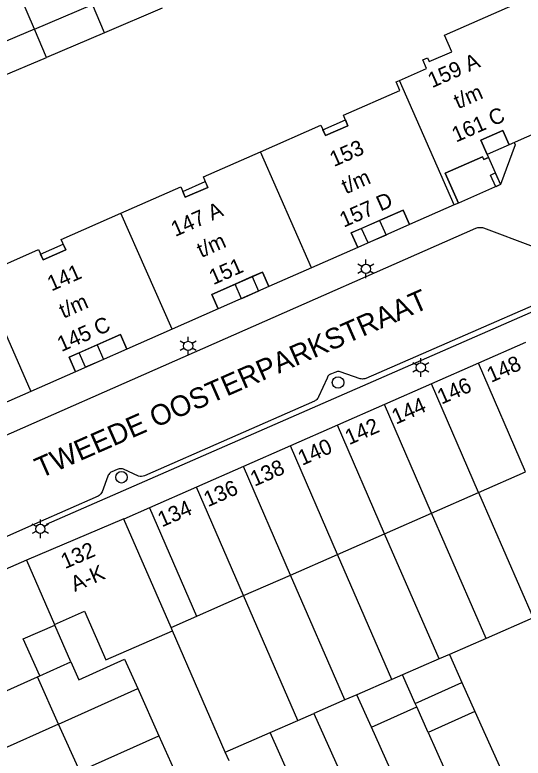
# Model space of a CAD drawing. Extents: x 122462 to 123306, y 485548 to 486417.
# Drawn here: x 123065.1 to 123114.5, y 485591 to 485663.3 of the extents above; entities that cross this region are included whole.
import ezdxf

# ---------------------------------------------------------------- set-up
doc = ezdxf.new("R2010")
doc.units = 0
for name, color, linetype in [('B-WE-IE-MEUBILAIR_WEGMEUBILAIR_VERKEERSBORD-S', 7, 'Continuous'), ('Level 1', 7, 'Continuous'), ('Level 10', 7, 'Continuous'), ('Level 11', 7, 'Continuous'), ('Level 17', 7, 'Continuous'), ('Level 19', 7, 'Continuous'), ('Level 2', 7, 'Continuous'), ('Level 30', 7, 'Continuous'), ('Level 34', 7, 'Continuous'), ('Level 4', 7, 'Continuous'), ('Level 50', 7, 'Continuous'), ('Level 53', 7, 'Continuous'), ('N-WE-AL-T25', 7, 'Continuous'), ('N-WE-GR-BOOM_DOORWORTELBARE RUIMTE-G', 7, 'Continuous')]:
    doc.layers.add(name, color=color, linetype=linetype)

msp = doc.modelspace()

# ---------------------------------------------------------------- linework, layer by layer
at = {"layer": 'Level 1'}
for p, q in [((123100.592, 485643.304), (123098.838, 485642.531)), ((123088.207, 485637.847), (123086.535, 485637.11)), ((123114.754, 485631.419), (123110.186, 485629.41)), ((123073.137, 485631.207), (123071.392, 485630.438)), ((123110.186, 485629.41), (123105.618, 485627.402)), ((123105.618, 485627.402), (123101.049, 485625.394)), ((123101.049, 485625.394), (123096.482, 485623.387)), ((123096.482, 485623.387), (123091.913, 485621.378)), ((123091.913, 485621.378), (123087.345, 485619.37)), ((123087.345, 485619.37), (123082.777, 485617.362)), ((123110.205, 485616.854), (123114.774, 485618.861)), ((123082.777, 485617.362), (123078.209, 485615.354)), ((123105.636, 485614.847), (123110.205, 485616.854)), ((123078.209, 485615.354), (123075.745, 485614.248)), ((123101.067, 485612.84), (123105.636, 485614.847)), ((123096.499, 485610.833), (123101.067, 485612.84)), ((123091.93, 485608.826), (123096.499, 485610.833)), ((123087.362, 485606.819), (123091.93, 485608.826)), ((123080.321, 485603.726), (123087.362, 485606.819)), ((123115.51, 485604.655), (123110.937, 485602.659)), ((123069.032, 485603.947), (123068.996, 485604.029)), ((123080.459, 485603.409), (123080.321, 485603.726)), ((123110.937, 485602.659), (123107.371, 485601.104)), ((123107.371, 485601.104), (123106.363, 485600.664)), ((123106.363, 485600.664), (123102.802, 485599.112)), ((123067.337, 485598.913), (123067.565, 485599.015)), ((123069.395, 485594.33), (123067.337, 485598.913)), ((123102.802, 485599.112), (123101.789, 485598.67)), ((123101.789, 485598.67), (123098.386, 485597.186)), ((123104.05, 485596.334), (123108.596, 485598.376)), ((123108.596, 485598.376), (123109.856, 485595.57)), ((123097.215, 485596.675), (123094.21, 485595.364)), ((123098.386, 485597.186), (123097.215, 485596.675)), ((123099.805, 485594.027), (123104.2, 485596.001)), ((123104.2, 485596.001), (123104.05, 485596.334)), ((123094.21, 485595.364), (123098.391, 485586.058)), ((123109.856, 485595.57), (123105.31, 485593.529)), ((123071.452, 485589.751), (123069.395, 485594.33)), ((123101.624, 485589.977), (123099.805, 485594.027)), ((123105.31, 485593.529), (123106.941, 485589.899))]:
    msp.add_line(p, q, dxfattribs=at)
for points in [[(123102.513, 485656.923), (123105.15, 485658.082), (123104.787, 485658.906), (123105.245, 485659.108), (123105.406, 485658.742), (123107.603, 485659.71), (123106.896, 485661.316), (123131.906, 485672.331), (123132.612, 485670.729), (123134.808, 485671.696), (123134.647, 485672.062), (123135.104, 485672.263), (123135.467, 485671.439), (123138.094, 485672.594)], [(123143.438, 485660.484), (123143.083, 485660.327), (123141.803, 485663.235), (123138.179, 485661.639), (123138.304, 485661.356), (123137.855, 485661.158), (123137.108, 485662.854), (123134.89, 485661.877), (123135.503, 485660.486), (123126.802, 485656.654), (123125.651, 485659.27), (123120.75, 485657.111), (123121.902, 485654.496), (123113.193, 485650.66), (123112.58, 485652.052), (123110.428, 485651.104), (123111.173, 485649.408), (123110.724, 485649.211), (123110.6, 485649.494), (123106.975, 485647.9), (123108.257, 485644.987), (123107.851, 485644.807)], [(123089.007, 485649.968), (123094.876, 485652.554), (123095.32, 485651.548), (123097.516, 485652.515), (123097.072, 485653.522), (123102.562, 485655.94), (123102.192, 485656.782), (123102.513, 485656.923)], [(123075.452, 485643.996), (123081.26, 485646.555), (123081.704, 485645.549), (123083.904, 485646.518), (123083.461, 485647.525), (123089.007, 485649.968)], [(123107.851, 485644.807), (123103.502, 485642.891), (123102.877, 485644.311), (123100.592, 485643.304)], [(123061.734, 485637.952), (123067.431, 485640.462), (123067.874, 485639.456), (123070.08, 485640.427), (123069.636, 485641.434), (123075.452, 485643.996)], [(123098.838, 485642.531), (123097.84, 485642.091), (123098.465, 485640.672), (123093.974, 485638.694)], [(123093.974, 485638.694), (123089.82, 485636.864), (123089.195, 485638.282), (123088.207, 485637.847)], [(123086.535, 485637.11), (123084.277, 485636.115), (123084.902, 485634.697), (123080.42, 485632.722)], [(123080.42, 485632.722), (123076.019, 485630.783), (123075.394, 485632.202), (123073.137, 485631.207)], [(123071.392, 485630.438), (123070.416, 485630.008), (123071.041, 485628.59), (123066.701, 485626.678)], [(123066.701, 485626.678), (123062.378, 485624.773), (123061.753, 485626.192), (123060.806, 485625.775)], [(123075.745, 485614.248), (123075.729, 485614.279), (123066.279, 485610.269)], [(123066.279, 485610.269), (123059.494, 485607.31), (123052.709, 485604.35), (123057.168, 485594.345)], [(123068.996, 485604.029), (123071.922, 485605.302), (123073.972, 485600.588), (123080.459, 485603.409)], [(123067.565, 485599.015), (123065.952, 485602.607), (123069.032, 485603.947)]]:
    msp.add_lwpolyline(points, dxfattribs=at)
at = {"layer": 'Level 10'}
for points in [[(123095.32, 485651.548), (123095.066, 485652.124), (123097.262, 485653.091), (123097.516, 485652.515), (123095.32, 485651.548)], [(123111.04, 485649.711), (123110.428, 485651.104), (123112.58, 485652.052), (123113.193, 485650.66), (123111.04, 485649.711)], [(123112.33, 485646.779), (123108.257, 485644.987), (123106.975, 485647.9), (123110.6, 485649.494), (123110.724, 485649.211), (123111.173, 485649.408), (123112.33, 485646.779)], [(123081.704, 485645.549), (123081.45, 485646.125), (123083.65, 485647.095), (123083.904, 485646.518), (123081.704, 485645.549)], [(123098.465, 485640.672), (123097.84, 485642.091), (123102.877, 485644.311), (123103.502, 485642.891), (123098.465, 485640.672)], [(123067.874, 485639.456), (123067.621, 485640.033), (123069.826, 485641.003), (123070.08, 485640.427), (123067.874, 485639.456)], [(123084.902, 485634.697), (123084.277, 485636.115), (123089.195, 485638.282), (123089.82, 485636.864), (123084.902, 485634.697)], [(123071.041, 485628.59), (123070.416, 485630.008), (123075.394, 485632.202), (123076.019, 485630.783), (123071.041, 485628.59)]]:
    msp.add_lwpolyline(points, dxfattribs=at)
at = {"layer": 'Level 11'}
msp.add_lwpolyline([(123113.663, 485650.867), (123113.762, 485650.642), (123112.33, 485646.779)], dxfattribs=at)
at = {"layer": 'Level 17'}
msp.add_line((123167.101, 485657.051), (123068.183, 485613.738), dxfattribs=at)
for points in [[(123059.035, 485620.111), (123109.941, 485642.545), (123110.044, 485642.584), (123110.151, 485642.612), (123110.26, 485642.627), (123110.37, 485642.63), (123110.48, 485642.622), (123110.588, 485642.601), (123110.693, 485642.568), (123115.505, 485640.78)], [(123116.786, 485635.597), (123108.895, 485632.144), (123099.244, 485627.943)], [(123099.244, 485627.943), (123099.138, 485627.909), (123099.028, 485627.889), (123098.917, 485627.882), (123098.806, 485627.889), (123098.697, 485627.91), (123096.759, 485628.582), (123096.672, 485628.603), (123096.583, 485628.611), (123096.493, 485628.607), (123096.405, 485628.591), (123096.32, 485628.563), (123096.239, 485628.524), (123095.913, 485628.394), (123095.827, 485628.37), (123095.745, 485628.331), (123095.672, 485628.28), (123095.607, 485628.218), (123095.554, 485628.146), (123095.513, 485628.066), (123095.486, 485627.98), (123094.65, 485626.139), (123094.606, 485626.053), (123094.551, 485625.973), (123094.487, 485625.901), (123094.413, 485625.838), (123094.333, 485625.785), (123094.246, 485625.742), (123077.738, 485618.461), (123077.597, 485618.43), (123077.453, 485618.413), (123077.309, 485618.412), (123077.165, 485618.427), (123075.689, 485619.107), (123075.592, 485619.136), (123075.493, 485619.153), (123075.392, 485619.157), (123075.291, 485619.149), (123075.193, 485619.129), (123075.097, 485619.096), (123074.553, 485618.857), (123074.469, 485618.811), (123074.392, 485618.754), (123074.322, 485618.688), (123074.262, 485618.614), (123074.212, 485618.532), (123074.172, 485618.445), (123073.619, 485616.904), (123073.56, 485616.806), (123073.49, 485616.716), (123073.411, 485616.634), (123073.322, 485616.562), (123073.225, 485616.501), (123067.352, 485613.901), (123058.667, 485610.037)]]:
    msp.add_lwpolyline(points, dxfattribs=at)
at = {"layer": 'Level 19'}
for p, q in [((123067.031, 485661.895), (123062.693, 485672.078)), ((123110.205, 485616.854), (123115.51, 485604.655)), ((123110.937, 485602.659), (123105.636, 485614.847)), ((123106.363, 485600.664), (123101.067, 485612.84)), ((123101.789, 485598.67), (123096.499, 485610.833)), ((123097.215, 485596.675), (123091.93, 485608.826)), ((123092.641, 485594.68), (123087.362, 485606.819)), ((123070.588, 485600.372), (123069.032, 485603.947)), ((123085.592, 485591.606), (123080.459, 485603.409)), ((123067.565, 485599.015), (123070.588, 485600.372)), ((123069.395, 485594.33), (123077.076, 485597.781)), ((123077.076, 485597.781), (123079.134, 485593.202)), ((123105.31, 485593.529), (123104.2, 485596.001)), ((123092.641, 485594.68), (123094.21, 485595.364)), ((123089.957, 485593.51), (123092.641, 485594.68)), ((123071.452, 485589.751), (123079.134, 485593.202)), ((123079.134, 485593.202), (123081.191, 485588.624)), ((123085.592, 485591.606), (123089.957, 485593.51)), ((123093.236, 485586.21), (123089.957, 485593.51)), ((123085.956, 485590.766), (123085.592, 485591.606))]:
    msp.add_line(p, q, dxfattribs=at)
msp.add_lwpolyline([(123070.588, 485600.372), (123071.34, 485598.644), (123075.789, 485600.644), (123077.076, 485597.781)], dxfattribs=at)
at = {"layer": 'Level 2'}
for p, q in [((123067.031, 485661.895), (123072.669, 485664.298)), ((123073.836, 485661.557), (123072.669, 485664.298)), ((123079.448, 485663.948), (123073.836, 485661.557)), ((123067.031, 485661.895), (123061.479, 485659.53)), ((123068.199, 485659.155), (123067.031, 485661.895)), ((123073.836, 485661.557), (123068.199, 485659.155)), ((123062.647, 485656.789), (123068.199, 485659.155))]:
    msp.add_line(p, q, dxfattribs=at)
at = {"layer": 'Level 30'}
for points in [[(123100.592, 485643.304), (123101.217, 485641.884), (123099.463, 485641.112), (123098.838, 485642.531)], [(123088.207, 485637.847), (123088.832, 485636.428), (123087.16, 485635.692), (123086.535, 485637.11)], [(123073.137, 485631.207), (123073.762, 485629.789), (123072.017, 485629.02), (123071.392, 485630.438)]]:
    msp.add_lwpolyline(points, dxfattribs=at)
at = {"layer": 'Level 34'}
msp.add_lwpolyline([(123111.882, 485646.583), (123111.382, 485647.718), (123111.831, 485647.916), (123112.33, 485646.779), (123111.882, 485646.583)], dxfattribs=at)
at = {"layer": 'Level 4'}
for p, q in [((123107.851, 485644.807), (123102.513, 485656.923)), ((123093.974, 485638.694), (123089.007, 485649.968)), ((123080.42, 485632.722), (123075.452, 485643.996)), ((123061.734, 485637.952), (123066.701, 485626.678)), ((123080.321, 485603.726), (123075.745, 485614.248)), ((123066.279, 485610.269), (123068.996, 485604.029)), ((123107.371, 485601.104), (123108.596, 485598.376)), ((123057.168, 485594.345), (123067.337, 485598.913)), ((123104.05, 485596.334), (123102.802, 485599.112)), ((123099.805, 485594.027), (123098.386, 485597.186)), ((123069.395, 485594.33), (123059.246, 485589.771))]:
    msp.add_line(p, q, dxfattribs=at)
at = {"layer": 'Level 50'}
for p, q in [((123099.262, 485639.038), (123099.262, 485639.488)), ((123098.872, 485638.813), (123098.482, 485639.038)), ((123100.041, 485639.038), (123099.651, 485638.813)), ((123098.872, 485638.363), (123098.482, 485638.138)), ((123099.262, 485637.688), (123099.262, 485638.138)), ((123100.041, 485638.138), (123099.651, 485638.363)), ((123081.59, 485631.324), (123081.2, 485631.549)), ((123081.98, 485631.549), (123081.98, 485631.999)), ((123082.759, 485631.549), (123082.369, 485631.324)), ((123081.59, 485630.874), (123081.2, 485630.649)), ((123081.98, 485630.199), (123081.98, 485630.649)), ((123082.759, 485630.649), (123082.369, 485630.874)), ((123104.591, 485629.456), (123104.591, 485629.906)), ((123104.201, 485629.231), (123103.811, 485629.456)), ((123105.37, 485629.456), (123104.98, 485629.231)), ((123104.201, 485628.781), (123103.811, 485628.556)), ((123104.591, 485628.106), (123104.591, 485628.556)), ((123105.37, 485628.556), (123104.98, 485628.781)), ((123067.616, 485613.759), (123067.616, 485614.209)), ((123067.226, 485613.534), (123066.836, 485613.759)), ((123068.395, 485613.759), (123068.005, 485613.534)), ((123067.226, 485613.084), (123066.836, 485612.859)), ((123067.616, 485612.409), (123067.616, 485612.859)), ((123068.395, 485612.859), (123068.005, 485613.084))]:
    msp.add_line(p, q, dxfattribs=at)
for centre in [(123099.262, 485638.588), (123081.98, 485631.099), (123104.591, 485629.006), (123067.616, 485613.309)]:
    msp.add_circle(centre, 0.45, dxfattribs=at)
at = {"layer": 'Level 53'}
for centre in [(123096.548, 485627.545), (123075.5, 485618.331)]:
    msp.add_circle(centre, 0.56, dxfattribs=at)
at = {"layer": 'N-WE-AL-T25'}
for p, q in [((123110.186, 485629.41), (123110.184, 485629.414)), ((123114.774, 485618.861), (123110.186, 485629.41)), ((123105.618, 485627.402), (123105.616, 485627.406)), ((123110.205, 485616.854), (123105.618, 485627.402)), ((123101.049, 485625.394), (123101.048, 485625.397)), ((123105.636, 485614.847), (123101.049, 485625.394)), ((123096.482, 485623.387), (123096.481, 485623.389)), ((123101.067, 485612.84), (123096.482, 485623.387)), ((123091.913, 485621.378), (123091.912, 485621.38)), ((123096.499, 485610.833), (123091.913, 485621.378)), ((123087.345, 485619.37), (123087.344, 485619.371)), ((123091.93, 485608.826), (123087.345, 485619.37)), ((123082.777, 485617.362), (123082.777, 485617.363)), ((123087.362, 485606.819), (123082.777, 485617.362)), ((123078.209, 485615.354), (123082.793, 485604.812)), ((123109.856, 485595.57), (123116.34, 485581.13))]:
    msp.add_line(p, q, dxfattribs=at)

# ---------------------------------------------------------------- texts
at = {"layer": 'B-WE-IE-MEUBILAIR_WEGMEUBILAIR_VERKEERSBORD-S'}
for s, rotation, p in [('159 A', 23.77023, (123105.688, 485656.152)), ('t/m', 23.77023, (123108.217, 485654.108)), ('161 C', 23.77023, (123108.018, 485650.863)), ('153', 23.77825, (123096.148, 485648.482)), ('t/m', 23.77825, (123097.305, 485645.835)), ('157 D', 23.77825, (123097.108, 485642.59)), ('147 A', 23.77825, (123080.724, 485641.687)), ('t/m', 23.77825, (123083.25, 485639.643)), ('151', 23.77825, (123084.422, 485637)), ('141', 23.77825, (123068.701, 485636.389)), ('t/m', 23.77825, (123069.86, 485633.743)), ('145 C', 23.77825, (123069.664, 485630.498)), ('148', 23.7154, (123111.424, 485627.503)), ('146', 23.7154, (123106.601, 485625.385)), ('144', 23.7154, (123102.176, 485623.441)), ('142', 23.7154, (123097.634, 485621.445)), ('140', 23.7154, (123093.058, 485619.435)), ('138', 23.7154, (123088.432, 485617.403)), ('136', 23.7154, (123083.902, 485615.413)), ('134', 23.7154, (123079.431, 485613.449)), ('132', 23.49459, (123070.015, 485609.389)), ('A-K', 23.49459, (123070.967, 485607.173))]:
    msp.add_text(s, height=1.5, rotation=rotation, dxfattribs=at).set_placement(p)
at = {"layer": 'N-WE-GR-BOOM_DOORWORTELBARE RUIMTE-G'}
msp.add_text('TWEEDE OOSTERPARKSTRAAT', height=2, rotation=23.74026, dxfattribs=at).set_placement((123067.641, 485618.211))

doc.saveas('drawing.dxf')
